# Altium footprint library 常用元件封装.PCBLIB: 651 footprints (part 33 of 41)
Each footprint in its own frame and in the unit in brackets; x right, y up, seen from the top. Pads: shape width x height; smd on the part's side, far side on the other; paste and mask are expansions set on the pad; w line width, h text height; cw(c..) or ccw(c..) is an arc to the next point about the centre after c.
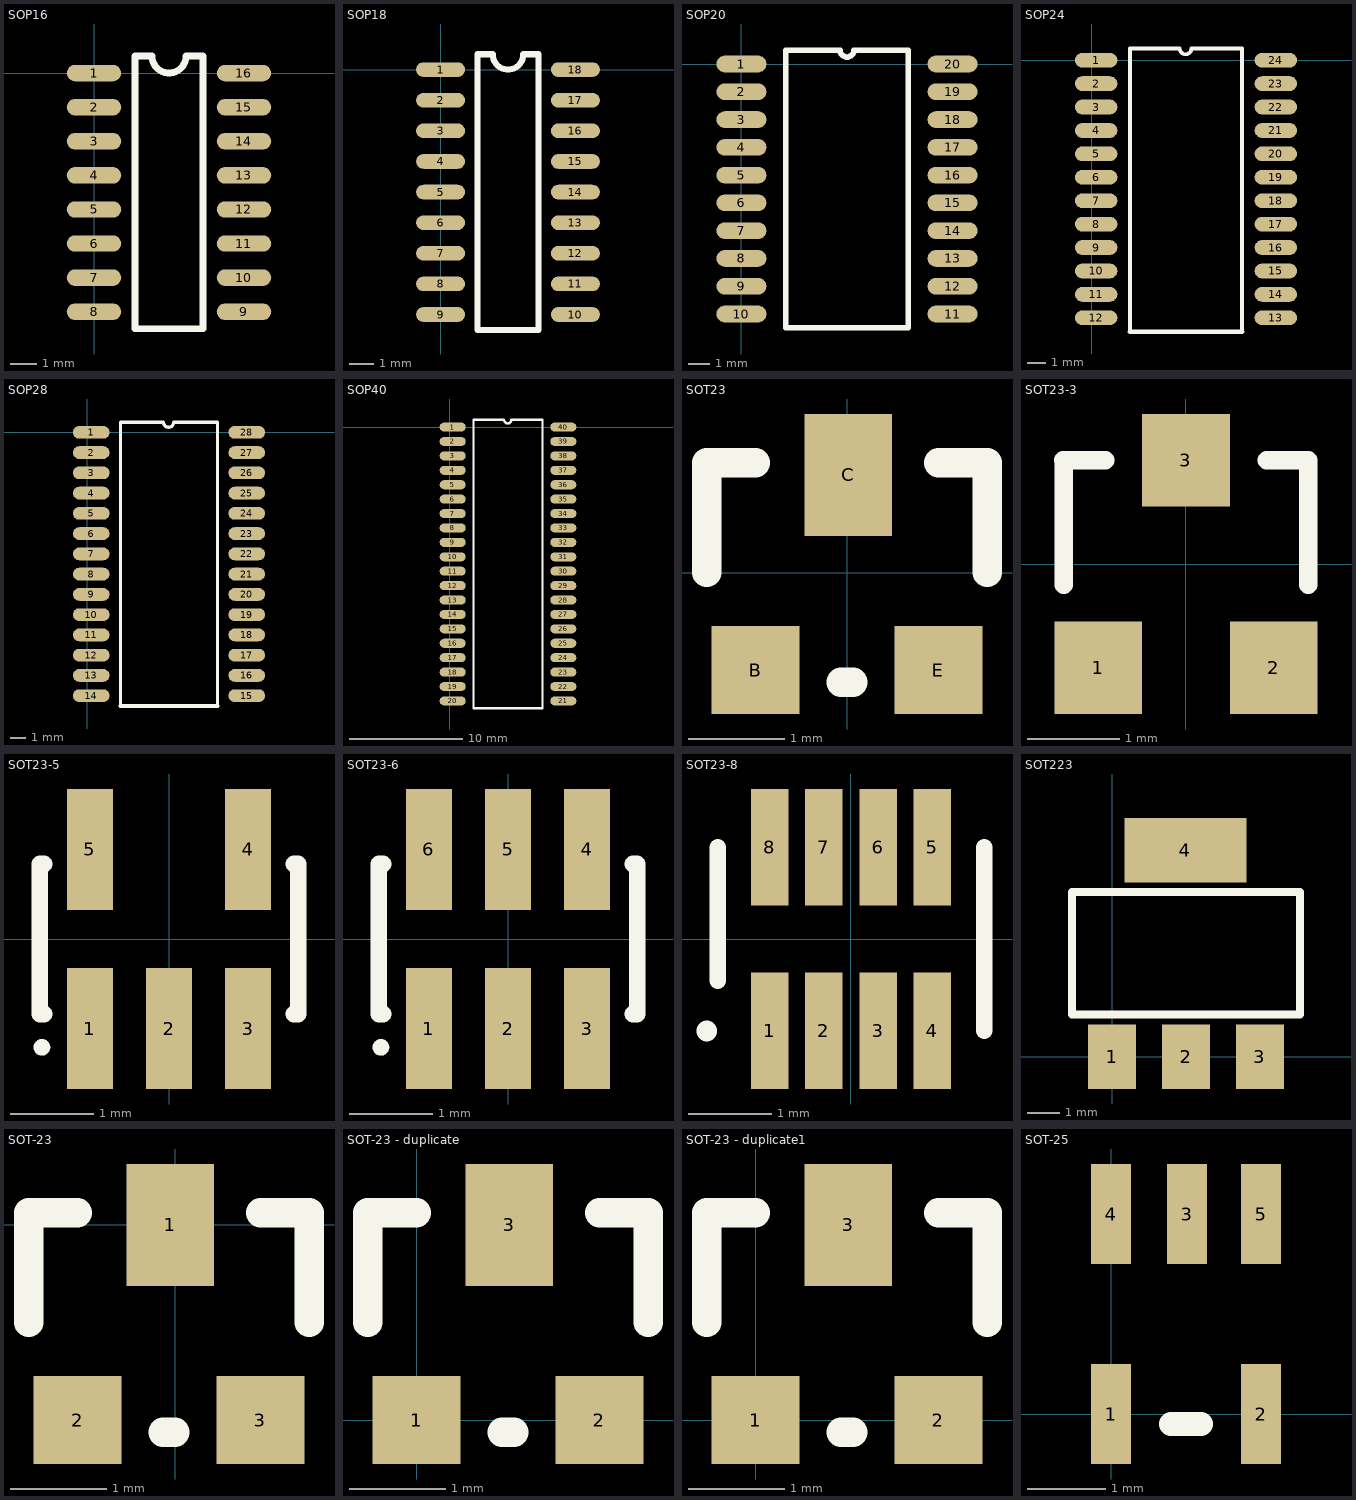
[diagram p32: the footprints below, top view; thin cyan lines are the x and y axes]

## SOP16 [mil]
pads (16):
  oval 80x24 smd: 1(0,0) 2(0,-50) 3(0,-100) 4(0,-150) 5(0,-200) 6(0,-250) 7(0,-300) 8(0,-350) 9(220,-350) 10(220,-300) 11(220,-250) 12(220,-200) 13(220,-150) 14(220,-100) 15(220,-50) 16(220,0)
TopOverlay:
  lines w10: 60,-375 160,-375 160,25 135,25 cw(c110,25) 85,25 60,25 60,-375

## SOP18 [mil]
pads (18):
  oval 80x24 smd: 1(0,0) 2(0,-50) 3(0,-100) 4(0,-150) 5(0,-200) 6(0,-250) 7(0,-300) 8(0,-350) 9(0,-400) 10(220,-400) 11(220,-350) 12(220,-300) 13(220,-250) 14(220,-200) 15(220,-150) 16(220,-100) 17(220,-50) 18(220,0)
TopOverlay:
  lines w10: 60,-425 160,-425 160,25 135,25 cw(c110,25) 85,25 60,25 60,-425

## SOP20 [mil]
pads (20):
  oval 90x30 smd: 1(0,0) 2(0,-50) 3(0,-100) 4(0,-150) 5(0,-200) 6(0,-250) 7(0,-300) 8(0,-350) 9(0,-400) 10(0,-450) 11(380,-450) 12(380,-400) 13(380,-350) 14(380,-300) 15(380,-250) 16(380,-200) 17(380,-150) 18(380,-100) 19(380,-50) 20(380,0)
TopOverlay:
  lines w10: 80,-475 80,25 177.5,25 ccw(c190,25) 202.5,25 300,25 300,-475 80,-475

## SOP24 [mm]
pads (24):
  oval 2.3x0.8 smd: 1(0.25,0) 2(0.25,-1.27) 3(0.25,-2.54) 4(0.25,-3.81) 5(0.25,-5.08) 6(0.25,-6.35) 7(0.25,-7.62) 8(0.25,-8.89) 9(0.25,-10.16) 10(0.25,-11.43) 11(0.25,-12.7) 12(0.25,-13.97) 13(10,-13.97) 14(10,-12.7) 15(10,-11.43) 16(10,-10.16) 17(10,-8.89) 18(10,-7.62) 19(10,-6.35) 20(10,-5.08) 21(10,-3.81) 22(10,-2.54) 23(10,-1.27) 24(10,0)
TopOverlay:
  lines w0.2: 2.085,-14.732 2.085,0.635 4.782,0.635 ccw(c5.1,0.635) 5.417,0.635 8.115,0.635 ; 8.165,-14.732 8.165,0.635
  lines w0.254: 2.085,-14.732 8.165,-14.732

## SOP28 [mm]
pads (28):
  oval 2.3x0.8 smd: 1(0.25,0) 2(0.25,-1.27) 3(0.25,-2.54) 4(0.25,-3.81) 5(0.25,-5.08) 6(0.25,-6.35) 7(0.25,-7.62) 8(0.25,-8.89) 9(0.25,-10.16) 10(0.25,-11.43) 11(0.25,-12.7) 12(0.25,-13.97) 13(0.25,-15.24) 14(0.25,-16.51) 15(10,-16.51) 16(10,-15.24) 17(10,-13.97) 18(10,-12.7) 19(10,-11.43) 20(10,-10.16) 21(10,-8.89) 22(10,-7.62) 23(10,-6.35) 24(10,-5.08) 25(10,-3.81) 26(10,-2.54) 27(10,-1.27) 28(10,0)
TopOverlay:
  lines w0.2: 2.085,-17.145 2.085,0.635 4.782,0.635 ccw(c5.1,0.635) 5.417,0.635 8.115,0.635 ; 8.165,-17.145 8.165,0.635
  lines w0.254: 2.085,-17.145 8.165,-17.145

## SOP40 [mm]
pads (40):
  oval 2.3x0.8 smd: 1(0.25,0) 2(0.25,-1.27) 3(0.25,-2.54) 4(0.25,-3.81) 5(0.25,-5.08) 6(0.25,-6.35) 7(0.25,-7.62) 8(0.25,-8.89) 9(0.25,-10.16) 10(0.25,-11.43) 11(0.25,-12.7) 12(0.25,-13.97) 13(0.25,-15.24) 14(0.25,-16.51) 15(0.25,-17.78) 16(0.25,-19.05) 17(0.25,-20.32) 18(0.25,-21.59) 19(0.25,-22.86) 20(0.25,-24.13) 21(10,-24.13) 22(10,-22.86) 23(10,-21.59) 24(10,-20.32) 25(10,-19.05) 26(10,-17.78) 27(10,-16.51) 28(10,-15.24) 29(10,-13.97) 30(10,-12.7) 31(10,-11.43) 32(10,-10.16) 33(10,-8.89) 34(10,-7.62) 35(10,-6.35) 36(10,-5.08) 37(10,-3.81) 38(10,-2.54) 39(10,-1.27) 40(10,0)
TopOverlay:
  lines w0.2: 8.115,-24.765 2.085,-24.765 2.085,0.635 4.782,0.635 ccw(c5.1,0.635) 5.417,0.635 8.115,0.635 ; 8.165,-24.765 8.165,0.635

## SOT23 [mil]
pads (3):
  rect 36x36 smd: B(-37.5,-40) E(37.5,-40)
  rect 36x50 smd: C(0.5,40)
TopOverlay:
  lines w12: -57.5,0 -57.5,45 -37.5,45 ; -2.5,-45 2.5,-45 ; 37.5,45 57.5,45 57.5,0

## SOT23-3 [mm] "SOT-23; 3 Leads; Body 3.0 x 2.5 mm, inc. leads (LxW max)"
height 1.2
pads (3):
  rect 0.95x1 smd: 1(-0.95,-1.125) 2(0.95,-1.125) 3(0,1.125)
TopOverlay:
  lines w0.2: -1.328,1.125 -0.875,1.125 ; -1.325,-0.225 -1.325,1.125 ; 0.875,1.125 1.325,1.125 1.325,-0.225

## SOT23-5 [mm] "SOT-23/SC-74A; 5 Leads; Body 3 x 3 mm, inc. leads (LxW max)"
height 1.45
pads (5):
  rect 0.55x1.45 smd: 1(-0.95,-1.075) 2(0,-1.075) 3(0.95,-1.075) 4(0.95,1.075) 5(-0.95,1.075)
TopOverlay:
  circle w0.1: c-1.525,-1.3 r0.05
  lines w0.2: -1.5,-0.9 -1.55,-0.9 -1.55,0.9 -1.5,0.9 ; 1.5,-0.9 1.55,-0.9 1.55,0.9 1.5,0.9

## SOT23-6 [mm] "SOT-457/SC-74; 6 Leads; Body 3 x 3 mm, inc. leads (LxW max)"
height 1.45
pads (6):
  rect 0.55x1.45 smd: 1(-0.95,-1.075) 2(0,-1.075) 3(0.95,-1.075) 4(0.95,1.075) 5(0,1.075) 6(-0.95,1.075)
TopOverlay:
  circle w0.1: c-1.525,-1.3 r0.05
  lines w0.2: -1.5,-0.9 -1.55,-0.9 -1.55,0.9 -1.5,0.9 ; 1.5,-0.9 1.55,-0.9 1.55,0.9 1.5,0.9

## SOT23-8 [mm] "SSOP; 8 Leads; Body Width 1.6 mm; Pitch 0.65 mm"
height 1.45
pads (8):
  rect 0.45x1.4 smd: 1(-0.975,-1.1) 2(-0.325,-1.1) 3(0.325,-1.1) 4(0.975,-1.1) 5(0.975,1.1) 6(0.325,1.1) 7(-0.325,1.1) 8(-0.975,1.1)
TopOverlay:
  lines w0.2: -1.6,-0.5 -1.6,1.1 ; 1.6,-1.1 1.6,1.1
  lines w0.25: -1.73,-1.104 ccw(c-1.75,-1.1) -1.73,-1.1

## SOT223 [mil]
pads (4):
  rect 59x79 smd: 1(0,0) 2(90.55,0) 3(181.1,0)
  rect 150x79 smd: 4(89.88,253.54)
TopOverlay:
  lines w10: -49.45,52 -49.45,202 230.55,202 230.55,52 -49.45,52

## SOT-23 [mil]
pads (3):
  rect 36x50 smd: 1(-2,0)
  rect 36x36 smd: 2(-40,-80) 3(35,-80)
TopOverlay:
  lines w12: -60,-40 -60,5 -40,5 ; -5,-85 0,-85 ; 35,5 55,5 55,-40

## SOT-23 - duplicate [mil]
pads (3):
  rect 36x36 smd: 1(0,0) 2(75,0)
  rect 36x50 smd: 3(38,80)
TopOverlay:
  lines w12: -20,40 -20,85 0,85 ; 35,-5 40,-5 ; 75,85 95,85 95,40

## SOT-23 - duplicate1 [mil]
pads (3):
  rect 36x36 smd: 1(0,0) 2(75,0)
  rect 36x50 smd: 3(38,80)
TopOverlay:
  lines w12: -20,40 -20,85 0,85 ; 35,-5 40,-5 ; 75,85 95,85 95,40

## SOT-25 [mil]
pads (5):
  rect 20x50 smd: 1(0,0) 2(75,0) 3(38,100) 4(0,100) 5(75,100)
TopOverlay:
  lines w12: 30,-5 45,-5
